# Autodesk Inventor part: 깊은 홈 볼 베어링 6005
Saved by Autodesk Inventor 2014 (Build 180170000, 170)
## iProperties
Created: 2026-04
Part Number: 깊은 홈 볼 베어링 6005
Material: 강철, 연강
Document SubType Name: Modeling
Designer: dg
Density: 7.86 g/cm^3
Appearance: 강철
Mass: 78.9841 g
Surface Area: 80.8467 cm^2
Volume: 10.0489 cm^3
Author: jhkim
Description: 깊은 그루브 볼 베어링
Creation Date: 2026-03-27
Sending System: Autodesk Inventor 2026
Preprocessor: ST-DEVELOPER v20.1
Author: dg
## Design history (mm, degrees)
node "깊은 홈 볼 베어링 60051"
body "Solid1"
node "Solid1_1"
node "Solid1_2"
node "Solid1_3"
node "Solid1_4"
node "Solid1_5"
node "Solid1_6"
node "Solid1_7"
node "Solid1_8"
node "Solid1_9"
node "Solid1_10"
node "Solid1_11"
node "기준1"
node "기준2"
node "기준3"
node "기준4"
node "기준5"
node "기준6"
node "기준7"
node "기준8"
node "기준9"
node "기준10"
node "기준11"
node "기준12"
